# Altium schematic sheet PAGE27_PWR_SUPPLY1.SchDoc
size 431 x 431 mm; SheetNumber: 28; SheetTotal: 28
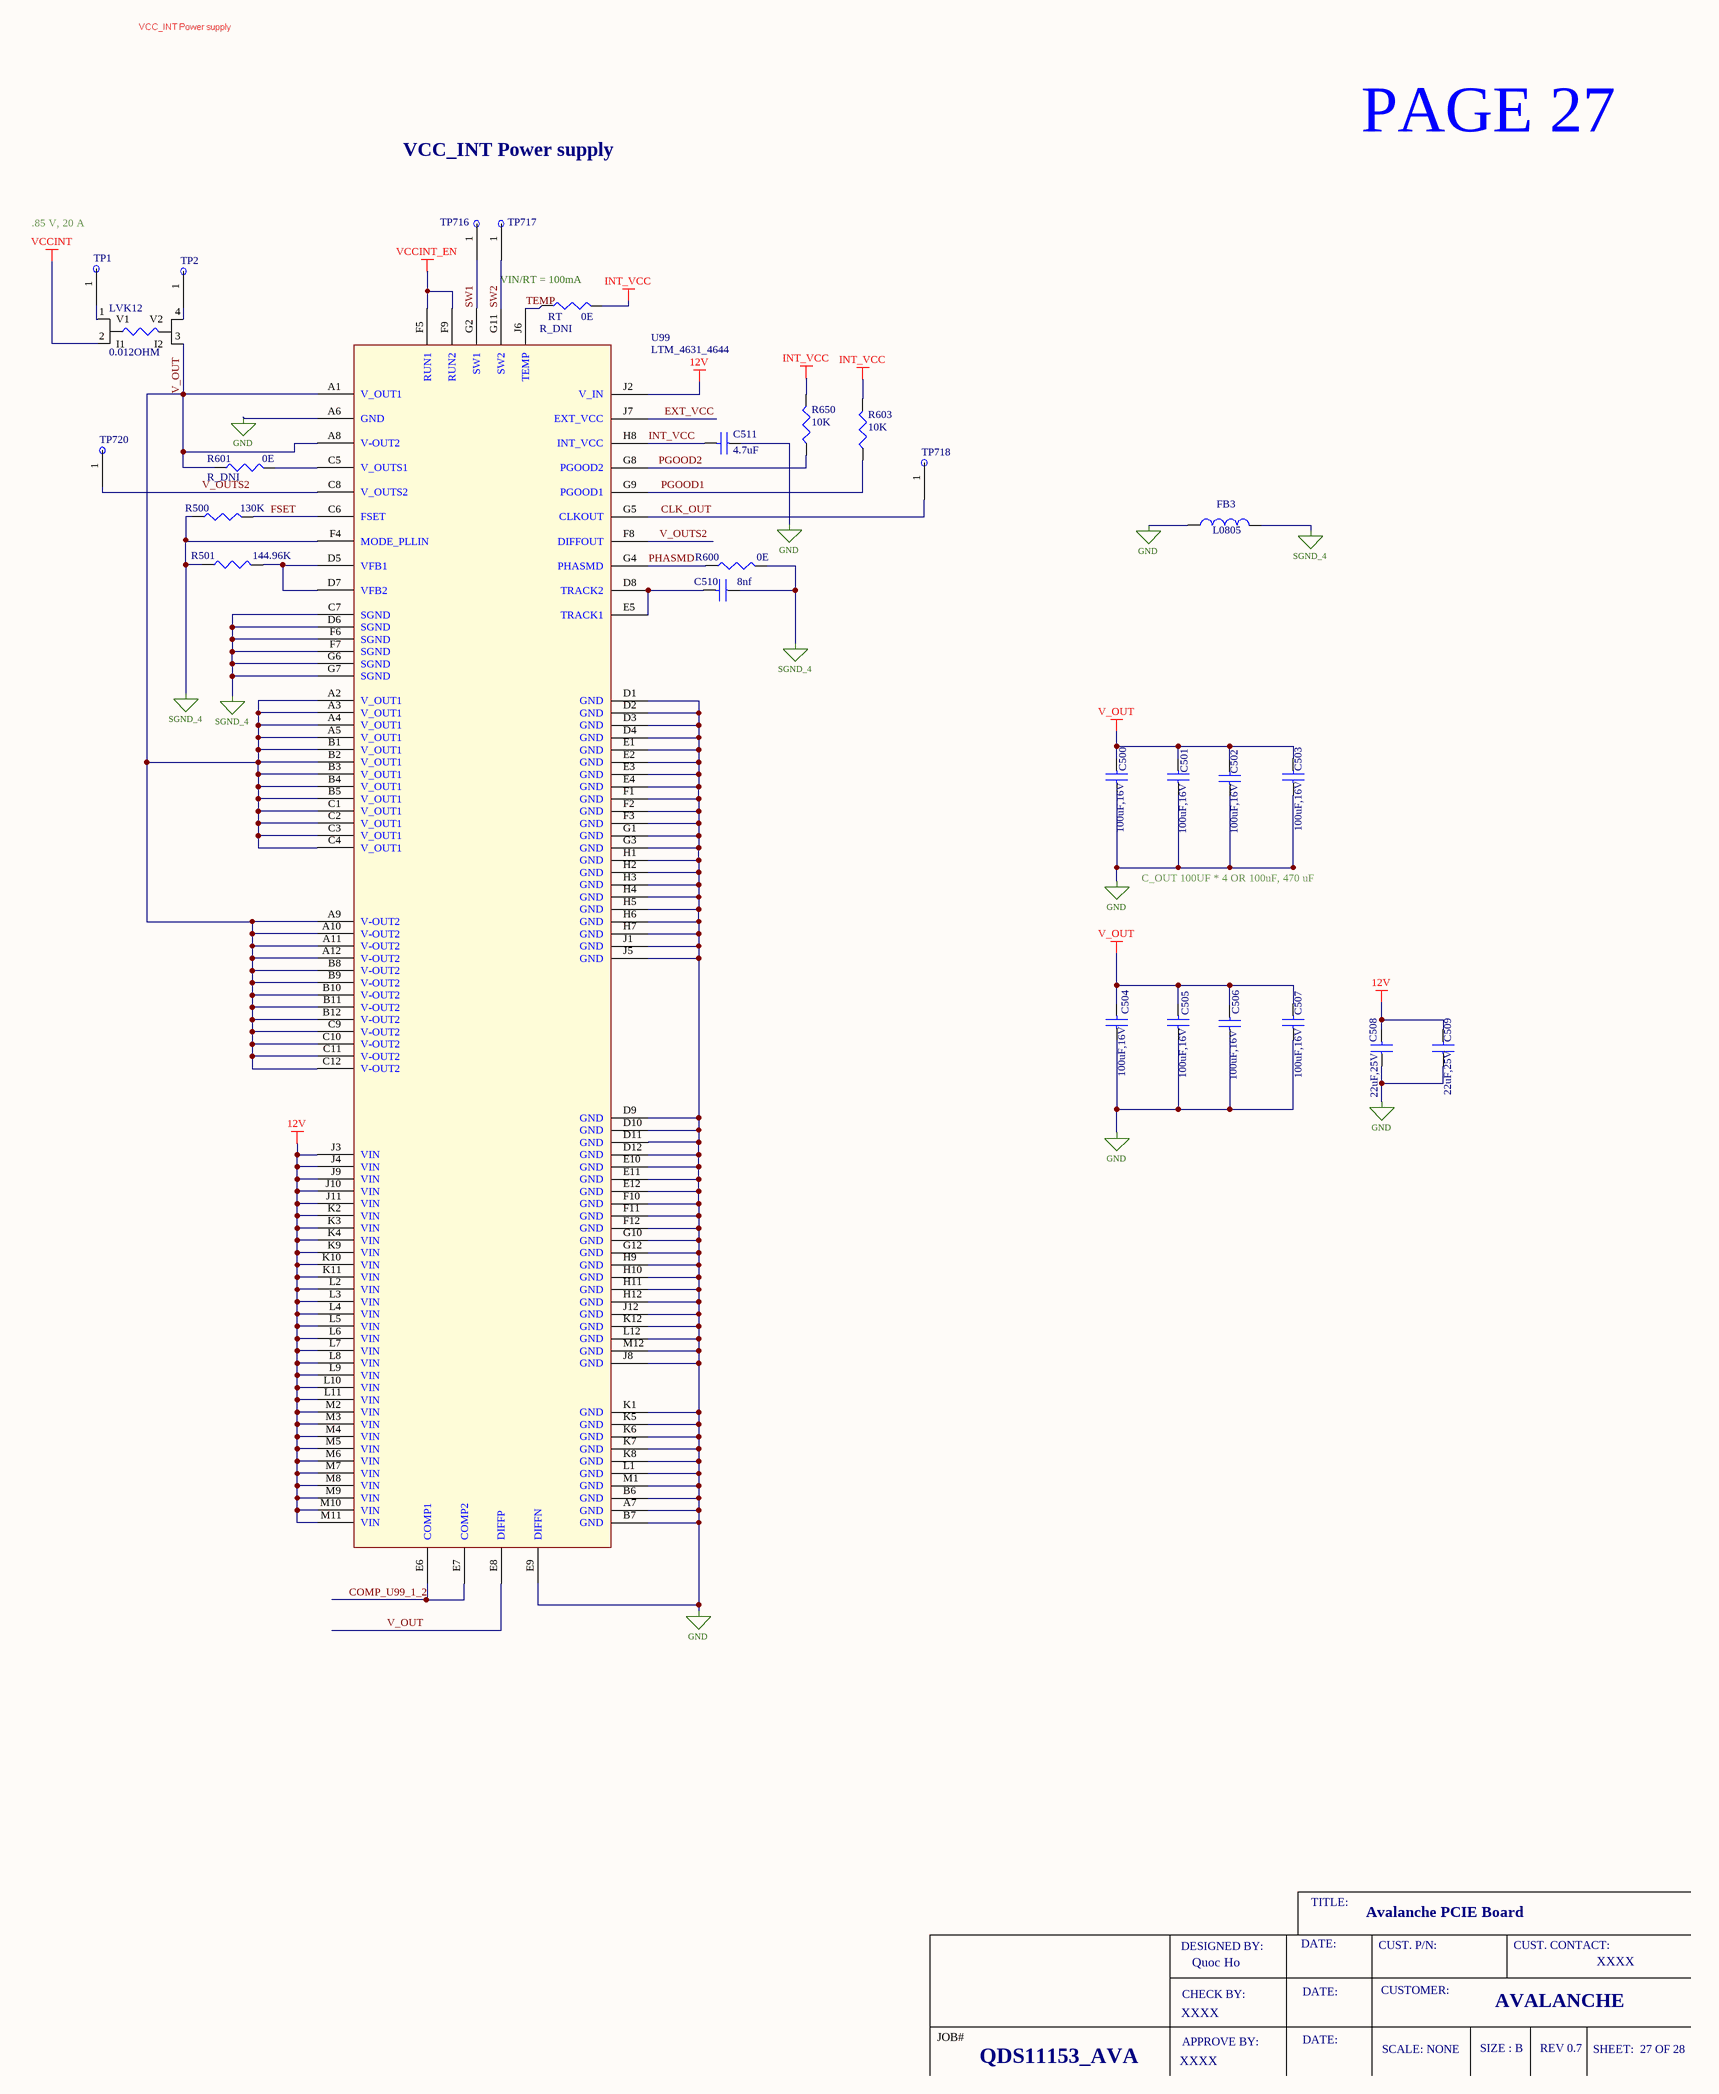
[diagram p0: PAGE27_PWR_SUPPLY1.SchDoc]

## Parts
C500  100uF,16V  [CN_1210]
C501  100uF,16V  [CN_1210]
C502  100uF,16V  [CN_1210]
C503  100uF,16V  [CN_1210]
C504  100uF,16V  [CN_1210]
C505  100uF,16V  [CN_1210]
C506  100uF,16V  [CN_1210]
C507  100uF,16V  [CN_1210]
C508  22uF,25V  [CN_1210]
C509  22uF,25V  [CN_1210]
C510  8nf  [CN_0402]
C511  4.7uF  [CN_0402]
FB3  L0805  [L0805]
LVK12  0.012OHM  [LVK12]
R500  130K  [RN_0402]
R501  144.96K  [RN_0402]
R600  0E  [RN_0402]
R601  0E  [RN_0402]
R603  10K  [RN_0402]
R650  10K  [RN_0402]
RT  0E  [RN_0402]
TP1  Tap_point  [MINI_TESTPOINT_SMD]  (value not drawn)
TP2  Tap_point  [MINI_TESTPOINT_SMD]  (value not drawn)
TP716  Tap_point  [MINI_TESTPOINT_SMD]  (value not drawn)
TP717  Tap_point  [MINI_TESTPOINT]  (value not drawn)
TP718  Tap_point  [MINI_TESTPOINT_SMD]  (value not drawn)
TP720  Tap_point  [MINI_TESTPOINT_SMD]  (value not drawn)
U99  LTM_4631_4644  [BGA144_16X16X1P91_1P91_ANA]

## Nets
12V: C508.2 C509.2 U99.J2(V_IN) U99.J3(VIN) U99.J4(VIN) U99.J9(VIN) U99.J10(VIN) U99.J11(VIN) U99.K2(VIN) U99.K3(VIN) U99.K4(VIN) U99.K9(VIN) U99.K10(VIN) U99.K11(VIN) U99.L2(VIN) U99.L3(VIN) U99.L4(VIN) U99.L5(VIN) U99.L6(VIN) U99.L7(VIN) U99.L8(VIN) U99.L9(VIN) U99.L10(VIN) U99.L11(VIN) U99.M2(VIN) U99.M3(VIN) U99.M4(VIN) U99.M5(VIN) U99.M6(VIN) U99.M7(VIN) U99.M8(VIN) U99.M9(VIN) U99.M10(VIN) U99.M11(VIN)
GND: C500.1 C501.1 C502.1 C503.1 C504.1 C505.1 C506.1 C507.1 C508.1 C509.1 C511.1 FB3.1 U99.A6(GND) U99.A7(GND) U99.B6(GND) U99.B7(GND) U99.D1(GND) U99.D2(GND) U99.D3(GND) U99.D4(GND) U99.D9(GND) U99.D10(GND) U99.D11(GND) U99.D12(GND) U99.E1(GND) U99.E2(GND) U99.E3(GND) U99.E4(GND) U99.E9(DIFFN) U99.E10(GND) U99.E11(GND) U99.E12(GND) U99.F1(GND) U99.F2(GND) U99.F3(GND) U99.F10(GND) U99.F11(GND) U99.F12(GND) U99.G1(GND) U99.G3(GND) U99.G10(GND) U99.G12(GND) U99.H1(GND) U99.H2(GND) U99.H3(GND) U99.H4(GND) U99.H5(GND) U99.H6(GND) U99.H7(GND) U99.H9(GND) U99.H10(GND) U99.H11(GND) U99.H12(GND) U99.J1(GND) U99.J5(GND) U99.J8(GND) U99.J12(GND) U99.K1(GND) U99.K5(GND) U99.K6(GND) U99.K7(GND) U99.K8(GND) U99.K12(GND) U99.L1(GND) U99.L12(GND) U99.M1(GND) U99.M12(GND)
INT_VCC: C511.2 R603.2 R650.2 RT.2 U99.H8(INT_VCC)
SGND_4: C510.1 FB3.2 R500.1 R501.1 R600.2 U99.C7(SGND) U99.D6(SGND) U99.F4(MODE_PLLIN) U99.F6(SGND) U99.F7(SGND) U99.G6(SGND) U99.G7(SGND)
V_OUT: C500.2 C501.2 C502.2 C503.2 C504.2 C505.2 C506.2 C507.2 LVK12.3(I2) R601.1 U99.A1(V_OUT1) U99.A2(V_OUT1) U99.A3(V_OUT1) U99.A4(V_OUT1) U99.A5(V_OUT1) U99.A8(V-OUT2) U99.A9(V-OUT2) U99.A10(V-OUT2) U99.A11(V-OUT2) U99.A12(V-OUT2) U99.B1(V_OUT1) U99.B2(V_OUT1) U99.B3(V_OUT1) U99.B4(V_OUT1) U99.B5(V_OUT1) U99.B8(V-OUT2) U99.B9(V-OUT2) U99.B10(V-OUT2) U99.B11(V-OUT2) U99.B12(V-OUT2) U99.C1(V_OUT1) U99.C2(V_OUT1) U99.C3(V_OUT1) U99.C4(V_OUT1) U99.C9(V-OUT2) U99.C10(V-OUT2) U99.C11(V-OUT2) U99.C12(V-OUT2) U99.E8(DIFFP)
VCCINT: LVK12.2(I1)
VCCINT_EN: U99.F5(RUN1) U99.F9(RUN2)
CLK_OUT: TP718.1 U99.G5(CLKOUT)
COMP_U99_1_2: U99.E6(COMP1) U99.E7(COMP2)
EXT_VCC: U99.J7(EXT_VCC)
FSET: R500.2 U99.C6(FSET)
PGOOD1: R603.1 U99.G9(PGOOD1)
PGOOD2: R650.1 U99.G8(PGOOD2)
PHASMD: R600.1 U99.G4(PHASMD)
SW1: TP716.1 U99.G2(SW1)
SW2: TP717.1 U99.G11(SW2)
TEMP: RT.1 U99.J6(TEMP)
V_OUTS2: TP720.1 U99.C8(V_OUTS2) U99.F8(DIFFOUT)
NetC510_2: C510.2 U99.D8(TRACK2) U99.E5(TRACK1)
NetLVK12_1: LVK12.1(V1) TP1.1
NetLVK12_4: LVK12.4(V2) TP2.1
NetR501_2: R501.2 U99.D5(VFB1) U99.D7(VFB2)
NetR601_2: R601.2 U99.C5(V_OUTS1)

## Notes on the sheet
- Text
- VCC_INT Power supply
- PAGE 27
- (near TP1) .85 V, 20 A
- (near RT) VIN/RT = 100mA
- C_OUT 100UF * 4 OR 100uF, 470 uF
- TITLE:
- Avalanche PCIE Board
- DESIGNED BY:
- CHECK BY:
- Quoc Ho
- DATE:
- CUST. P/N:
- CUSTOMER:
- CUST. CONTACT:
- XXXX
- JOB#
- APPROVE BY:
- SCALE: NONE
- SIZE : B
- AVALANCHE
- REV 0.7
- SHEET:  27 OF 28
- QDS11153_AVA

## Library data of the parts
C500-C507 = CAP: CAP CER 100UF 16V X5R 1210; Manufacturer: KYOCERA AVX; Manufacturer Part Number: 1210YD107MAT2A
C508 C509 = CAP: CAP CER 22UF 25V X5R 1210; Manufacturer Part Number: CL32A226KAJNNNE; Manufacturer: Samsung Electro-Mechanics
C510 = CAP: CAP CER 8200PF 25V X7R 0402; Manufacturer Part Number: C0402C822J3RACTU; Manufacturer: KEMET
C511 = CAP: CAP CER 4.7UF 25V X5S 0402; Manufacturer: Murata Electronics; Manufacturer Part Number: GRM155C61E475ME15J
FB3 = INDUCTOR: FERRITE BEAD 110 OHM 0805 1LN; Manufacturer Part Number: BLM21SP111SZ1D; Manufacturer: Murata Electronics
LVK12 = LVK24: RES 0.012OHM 1% 1/2W 1206; Manufacturer: OHMITE
R500 = RES: RES 130K OHM 1% 1/16W 0402; Manufacturer Part Number: RC0402FR-07130KL; Manufacturer: YAGEO
R501 = RES: RES 143K OHM 1% 1/16W 0402; Manufacturer Part Number: RC0402FR-07143KL; Manufacturer: YAGEO
R600 = RES: RES 0 OHM JUMPER 1/16W 0402; Manufacturer Part Number: RC0402JR-070RL; Manufacturer: YAGEO
R601 = RES: RES 0 OHM JUMPER 1/16W 0402; Manufacturer: YAGEO; Manufacturer Part Number: RC0402FR-070RL_DNI
R603 R650 = RES: RES 10K OHM 1% 1/16W 0402; Manufacturer Part Number: RC0402FR-0710KL; Manufacturer: YAGEO
RT = RES: RES 0 OHM JUMPER 1/16W 0402; Manufacturer Part Number: RC0402FR-070RL_DNI; Manufacturer: YAGEO
TP1 TP2 TP716-TP718 TP720 = Tap_point: Tap_point 15X25
U99 = LTM_4631_4644: DC DC CONVERTER 0.6V TO 1.8V; Manufacturer Part Number: LTM4631EV#PBF; Manufacturer: ANALOG DEVICES INC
